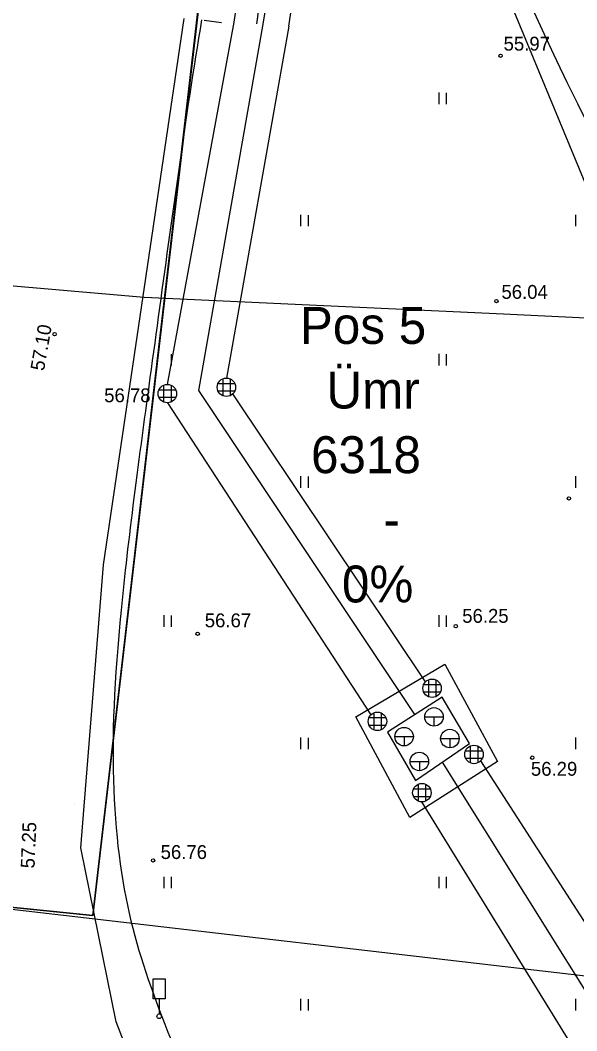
# Model space of a CAD drawing. Extents: x 9156 to 9809, y 2728 to 4000.
# Drawn here: x 9406.2 to 9436.3, y 3770.4 to 3825.1 of the extents above; entities that cross this region are included whole.
import ezdxf

# ---------------------------------------------------------------- set-up
doc = ezdxf.new("R2010")
doc.units = 0
for name, color, linetype in [('Level 17', 7, 'Continuous'), ('Level 18', 7, 'Continuous'), ('Level 5', 7, 'Continuous'), ('Level 54', 7, 'Continuous'), ('Level 56', 7, 'Continuous'), ('Level 6', 7, 'Continuous'), ('Level 7', 7, 'Continuous')]:
    doc.layers.add(name, color=color, linetype=linetype)

msp = doc.modelspace()

# ---------------------------------------------------------------- linework, layer by layer
at = {"layer": 'Level 17'}
for radius, start, end in [(226, 185.96508, 207.05054), (223, 186.63117, 207.05059)]:
    msp.add_arc((9639.344, 3919.894), radius, start, end, dxfattribs=at)
at = {"layer": 'Level 18'}
msp.add_arc((9639.344, 3919.894), 220, 188.1609, 207.05049, dxfattribs=at)
at = {"layer": 'Level 54'}
for p, q in [((9420.75, 3838.705), (9418.955, 3824.932)), ((9417.739, 3825.02), (9419.277, 3835.055)), ((9420.7, 3824.806), (9422.096, 3833.885)), ((9414.124, 3805.412), (9417.734, 3825.031)), ((9416.125, 3825.124), (9417.06, 3824.999)), ((9420.698, 3824.811), (9417.321, 3805.756)), ((9428.811, 3821.21), (9428.811, 3820.59)), ((9429.216, 3821.199), (9429.216, 3820.59)), ((9421.335, 3814.59), (9421.335, 3813.97)), ((9421.74, 3814.579), (9421.74, 3813.97)), ((9436.216, 3814.59), (9436.216, 3813.97)), ((9412.826, 3810.534), (9412.826, 3810.534)), ((9414.335, 3807.048), (9414.335, 3806.439)), ((9428.811, 3807.059), (9428.811, 3806.439)), ((9429.216, 3807.048), (9429.216, 3806.439)), ((9417.121, 3805.715), (9417.121, 3804.798)), ((9417.521, 3805.715), (9417.521, 3804.798)), ((9413.666, 3805.112), (9414.582, 3805.112)), ((9413.924, 3805.37), (9413.924, 3804.453)), ((9414.324, 3805.37), (9414.324, 3804.453)), ((9416.863, 3805.456), (9417.779, 3805.456)), ((9416.863, 3805.056), (9417.779, 3805.056)), ((9413.666, 3804.712), (9414.582, 3804.712)), ((9414.124, 3804.412), (9425.143, 3787.52)), ((9428.1, 3789.313), (9417.675, 3804.903)), ((9411.227, 3800.041), (9411.227, 3800.041)), ((9421.335, 3800.439), (9421.335, 3799.819)), ((9421.74, 3800.428), (9421.74, 3799.819)), ((9436.216, 3800.439), (9436.216, 3799.819)), ((9410.66, 3795.64), (9410.66, 3795.64)), ((9413.929, 3792.908), (9413.929, 3792.288)), ((9414.335, 3792.897), (9414.335, 3792.288)), ((9428.811, 3792.908), (9428.811, 3792.288)), ((9429.216, 3792.897), (9429.216, 3792.288)), ((9410.144, 3791.694), (9410.144, 3791.694)), ((9424.328, 3787.408), (9429.141, 3790.27)), ((9429.141, 3790.27), (9431.995, 3784.994)), ((9427.995, 3789.159), (9428.912, 3789.159)), ((9428.254, 3789.418), (9428.254, 3788.501)), ((9428.654, 3789.418), (9428.654, 3788.501)), ((9427.995, 3788.759), (9428.912, 3788.759)), ((9429.004, 3788.477), (9426.047, 3786.58)), ((9430.482, 3785.96), (9429.004, 3788.477)), ((9425.297, 3787.625), (9425.297, 3786.708)), ((9425.697, 3787.625), (9425.697, 3786.708)), ((9427.25, 3781.96), (9424.328, 3787.408)), ((9425.039, 3787.367), (9425.955, 3787.367)), ((9425.039, 3786.967), (9425.955, 3786.967)), ((9428.057, 3787.408), (9429.057, 3787.408)), ((9428.557, 3787.408), (9428.557, 3786.908)), ((9426.047, 3786.58), (9427.56, 3783.96)), ((9421.335, 3786.288), (9421.335, 3785.668)), ((9421.74, 3786.277), (9421.74, 3785.668)), ((9426.441, 3786.339), (9427.441, 3786.339)), ((9426.941, 3786.339), (9426.941, 3785.839)), ((9427.56, 3783.96), (9430.482, 3785.96)), ((9428.916, 3786.236), (9429.916, 3786.236)), ((9429.416, 3786.236), (9429.416, 3785.736)), ((9430.523, 3785.832), (9430.523, 3784.915)), ((9430.923, 3785.832), (9430.923, 3784.915)), ((9436.216, 3786.288), (9436.216, 3785.668)), ((9430.264, 3785.574), (9431.181, 3785.574)), ((9431.995, 3784.994), (9427.25, 3781.96)), ((9427.266, 3784.994), (9428.266, 3784.994)), ((9427.766, 3784.994), (9427.766, 3784.494)), ((9430.264, 3785.174), (9431.181, 3785.174)), ((9431.076, 3785.02), (9439.369, 3772.163)), ((9427.703, 3783.763), (9427.703, 3782.847)), ((9428.103, 3783.763), (9428.103, 3782.847)), ((9427.445, 3783.505), (9428.362, 3783.505)), ((9427.445, 3783.105), (9428.362, 3783.105)), ((9409.08, 3782.669), (9409.08, 3782.669)), ((9436.069, 3769.543), (9427.903, 3782.805)), ((9409.441, 3780.316), (9409.441, 3780.316)), ((9413.929, 3778.757), (9413.929, 3778.136)), ((9414.335, 3778.745), (9414.335, 3778.136)), ((9428.811, 3778.757), (9428.811, 3778.136)), ((9429.216, 3778.745), (9429.216, 3778.136)), ((9409.583, 3777.977), (9409.583, 3777.977)), ((9410.8, 3772.722), (9410.8, 3772.722)), ((9413.68, 3772.147), (9413.68, 3771.323)), ((9421.335, 3772.136), (9421.335, 3771.516)), ((9421.74, 3772.125), (9421.74, 3771.516)), ((9436.216, 3772.136), (9436.216, 3771.516)), ((9411.358, 3770.89), (9411.358, 3770.89))]:
    msp.add_line(p, q, dxfattribs=at)
for points in [[(9419.311, 3824.906), (9430.024, 3890.161), (9433.2, 3889.656), (9434.423, 3896.884), (9431.507, 3897.561), (9431.927, 3902.125)], [(9430.118, 3737.47), (9419.84, 3752.661), (9416.921, 3758.115), (9414.288, 3763.295), (9411.358, 3770.89), (9409.441, 3780.316), (9410.66, 3795.64), (9415.037, 3825.215)], [(9427.525, 3787.529), (9415.834, 3805.074), (9419.313, 3824.914)], [(9449.477, 3808.39), (9432.322, 3809.209), (9412.866, 3810.111), (9397.661, 3811.43), (9389.031, 3811.914)], [(9481.999, 3761.308), (9438.003, 3770.592), (9429.016, 3784.957)]]:
    msp.add_lwpolyline(points, dxfattribs=at)
msp.add_lwpolyline([(9413.364, 3773.224), (9413.997, 3773.224), (9413.997, 3772.147), (9413.364, 3772.147)], close=True, dxfattribs=at)
for centre, radius in [((9432.165, 3823.203), 0.0909), ((9431.938, 3809.92), 0.0909), ((9408.02, 3808.129), 0.0909), ((9417.321, 3805.256), 0.5), ((9414.124, 3804.912), 0.5), ((9435.863, 3799.237), 0.0909), ((9429.734, 3792.321), 0.0909), ((9415.764, 3791.913), 0.0909), ((9428.454, 3788.959), 0.5), ((9425.497, 3787.167), 0.5), ((9428.557, 3787.408), 0.5), ((9426.941, 3786.339), 0.5), ((9429.416, 3786.236), 0.5), ((9430.723, 3785.374), 0.5), ((9427.766, 3784.994), 0.5), ((9433.875, 3785.2), 0.0909), ((9427.903, 3783.305), 0.5), ((9413.352, 3779.634), 0.0909), ((9413.68, 3771.196), 0.126)]:
    msp.add_circle(centre, radius, dxfattribs=at)
msp.add_open_spline([(9415.976, 3825.147), (9415.093, 3819.866), (9413.578, 3808.546), (9411.641, 3794.709), (9410.924, 3784.763), (9411.76, 3776.853), (9413.792, 3771.101), (9417.009, 3763.374), (9419.226, 3759.393), (9422.553, 3753.458)], degree=3, dxfattribs=at)
at = {"layer": 'Level 56'}
for radius, start, end in [(226, 185.96508, 207.05054), (223, 186.63117, 207.05059), (220, 188.1609, 207.05049)]:
    msp.add_arc((9639.344, 3919.894), radius, start, end, dxfattribs=at)
at = {"layer": 'Level 6'}
msp.add_lwpolyline([(9406.335, 3871.284), (9417.264, 3870.77), (9419.931, 3861.081), (9410.086, 3776.653), (9389.428, 3778.75), (9392.066, 3801.386), (9401.769, 3871.605)], close=True, dxfattribs=at)
msp.add_lwpolyline([(9397.586, 3777.922), (9410.086, 3776.653), (9418.608, 3850.018)], dxfattribs=at)
at = {"layer": 'Level 7'}
for p, q in [((9423.602, 3847.995), (9436.729, 3816.345)), ((9453.674, 3771.409), (9312.256, 3787.831))]:
    msp.add_line(p, q, dxfattribs=at)

# ---------------------------------------------------------------- texts
at = {"layer": 'Level 5'}
for s, p in [('Pos 5', (9421.297, 3807.604)), ('Ümr', (9422.734, 3804.104)), ('6318', (9421.9, 3800.604)), ('-', (9425.827, 3797.104)), ('0%', (9423.575, 3793.604))]:
    msp.add_text(s, height=2, dxfattribs=at).set_placement(p)
at = {"layer": 'Level 54'}
for s, p in [('55.97', (9432.327, 3823.483)), ('56.04', (9432.209, 3810.043)), ('56.78', (9410.705, 3804.445)), ('56.67', (9416.149, 3792.259)), ('56.25', (9430.087, 3792.503)), ('56.29', (9433.804, 3784.221)), ('56.76', (9413.76, 3779.714))]:
    msp.add_text(s, height=0.75, dxfattribs=at).set_placement(p)
for s, rotation, p in [('57.10', 80.1005, (9407.443, 3806.109)), ('57.25', 87.6209, (9406.933, 3779.197))]:
    msp.add_text(s, height=0.75, rotation=rotation, dxfattribs=at).set_placement(p)

doc.saveas('drawing.dxf')
